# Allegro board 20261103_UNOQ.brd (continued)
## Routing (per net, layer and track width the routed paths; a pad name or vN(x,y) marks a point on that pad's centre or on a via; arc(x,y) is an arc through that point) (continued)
VREG_L4A_2P96V: length 46.4
  TOP w0.2: v2(37.96,12.08) 37.96,13.32 PMIC1.Y14
  G2 w0.203: v2(37.96,12.08) v3(39.02,12.08)
  S3 w0.2: v3(25.78,33.67) 25.77,33.67 v4(25.77,33.96)
  S3 w0.203: v3(39.02,12.08) v4(39.02,11.79)
  S6 w0.3: v4(39.02,11.79) 39.37,11.44 39.37,10.62 38.86,10.11 27.37,10.11 21.75,15.73 21.75,32.01 22.14,32.41 25.11,32.41 25.55,32.85 25.55,33.74 v4(25.77,33.96) 25.77,34.11 v1(25.67,34.21)
VREG_L5A_1P232V: length 6.6
  TOP w0.16: 33.07,14.15 33.88,14.96 33.88,14.96 34.05,15.13 34.05,15.13 PMIC1.P2
  TOP w0.2: v3(32.94,14.15) 33.07,14.15
  TOP w0.203: v3(33.45,34.41) 33.38,34.48 SOC1.F15 ; SOC1.AB11 26.97,36.25 v3(26.92,36.3) 26.97,36.36 SOC1.AB10
  S3 w0.127: 27.17,36.29 27.15,36.26 27.13,36.26 27.03,36.16 27.03,36.15 v3(26.97,36.08) ; 27.17,36.29 27.21,36.32 27.23,36.32 27.23,36.39 27.19,36.39 27.19,36.38 v4(27.18,36.38) ; 27.17,36.29 26.99,36.29 26.97,36.31 26.92,36.31 26.92,36.3 v3(26.92,36.3)
  S3 w0.2: v3(30.65,30.98) 30.57,30.98 30.57,31.06 v4(30.45,31.18) 30.35,31.28 v3(30.17,31.28) ; v4(33.82,34.29) 33.82,34.29 33.82,34.3 33.81,34.3 33.81,34.3 33.56,34.3 v3(33.45,34.41) ; v3(29.37,37.68) 29.37,37.63 29.55,37.45 v4(29.55,37.45) 29.77,37.66 v3(29.77,37.68)
  S3 w0.304: v3(32.94,14.15) 32.27,14.15 32.27,14.16 v4(32.27,14.16)
  S6 w0.2: v4(33.82,34.29) 33.82,34.29 33.82,34.3 33.81,34.3 33.66,34.15 v1(33.56,34.15)
  G7 w0.2: v1(29.29,37.68) v1(29.83,37.68)
  BOTTOM w0.203: C1934.1 33.52,34.15 33.53,34.15 v1(33.56,34.15)
  vias: v1(26.37,36.69) v1(26.92,36.66) v1(26.92,36.14) v1(30.63,31.54) v1(30.57,30.93) v1(30.6,30.49) v5(26.37,36.69) v5(26.92,36.66) v5(26.92,36.14) v5(30.63,31.54) v5(30.57,30.93) v5(30.6,30.49)
VREG_L6A_0P9V: length 33.7
  TOP w0.16: PMIC1.R1 34.16,14.76 34.01,14.61
  TOP w0.2: 34.01,14.61 33.05,13.64 C814.1
  S3 w0.127: v3(32.97,34.48) 33.09,34.36 33.09,34.24 v4(33.1,34.24)
  S3 w0.2: v4(30.04,30.48) v3(29.77,30.48)
  S3 w0.304: v3(32.94,13.75) 32.93,13.76 v4(32.61,13.76)
  S6 w0.2: 33.16,34.28 33.35,34.48 v1(33.35,34.63) 33.35,34.9 v1(33.3,34.95) ; 33.16,34.28 33.07,34.19 33.07,34.26 33.08,34.26 33.08,34.24 v4(33.1,34.24) ; 33.16,34.28 33.16,34.19 33.48,33.87 33.92,33.87 v5(34.32,33.48)
  S6 w0.3: 30.4,14.61 30.84,15.04 30.84,27.04 30.09,27.78 30.09,30.15 30.19,30.25 v1(30.19,30.25) 30.04,30.4 v4(30.04,30.48)
  S6 w0.304: v4(32.61,13.76) 30.69,13.76 30.4,14.05 30.4,14.61
  G7 w0.3: v5(34.32,33.48) 34.65,33.15 34.65,29.58 34.38,29.32 30.87,29.32 30.19,29.99 v1(30.19,30.25)
VREG_L7A_0P664V: length 4.3
  TOP w0.06: 32.96,14.66 v3(33.02,14.59)
  TOP w0.15: v3(33.02,14.59) 33.11,14.59 33.17,14.66 ; PMIC1.N3 34.14,15.41
  TOP w0.2: v3(32.17,36.08) v3(32.17,36.48) ; C815.1 33.17,14.66 33.93,15.41 34.14,15.41
  S3 w0.2: v4(32.17,37.16) v3(32.17,36.88)
  S3 w0.254: v4(33.3,14.59) 33.09,14.59 v3(33.02,14.59)
  V5 w0.3: v4(32.17,37.16) 32.17,36.76 v4(31.89,36.48)
  BOTTOM w0.05: C1845.1 32.26,37.55
  BOTTOM w0.203: v1(32.3,37.46) 32.26,37.46 32.26,37.49 32.26,37.55
  vias: v1(31.65,36.66) v1(32.2,36.6) v5(31.65,36.66) v5(32.2,36.6)
VREG_L8A_1P0V: length 5.3
  TOP w0.18: PMIC1.J5 35.29,16.55 34.61,16.55
  TOP w0.2: 34.61,16.55 34.43,16.37 33.54,16.37 ; v3(28.17,34.08) v3(28.17,33.68)
  TOP w0.254: 33.54,16.37 33.22,16.05 v3(31.88,16.05)
  S3 w0.2: v3(28.17,33.68) 28.2,33.68 v4(28.4,33.89) ; v3(31.88,16.05) v4(31.88,16.33)
  V5 w0.2: v4(28.4,33.89) 28.06,33.89 v4(27.87,34.08)
  S6 w0.203: v1(28.81,33.93) 28.83,33.93 28.83,33.93 28.85,33.93 28.85,33.93
  vias: v1(28.21,34.11) v5(28.21,34.11)
VREG_L9A_1P0V: length 4.1
  TOP w0.2: C817.1 33.3,15.67 33.7,16.07 34.64,16.07 PMIC1.L3
  S3 w0.2: v3(32.94,15.75) v4(32.94,16.08) ; v4(27.47,33.68) v3(27.77,33.68)
  S6 w0.2: v1(27.21,33.58) 27.22,33.58 27.22,33.58 27.2,33.58 27.24,33.54 27.33,33.54 v4(27.47,33.68)
  BOTTOM w0.2: C1828.1 27.25,33.52 C1827.1 C1826.1
  vias: v1(26.24,33.48) v5(26.24,33.48)
VREG_L10A_1P3V: length 54
  TOP w0.05: v3(32.26,37.67) 32.22,37.67 32.21,37.68 SOC1.J7
  TOP w0.16: PMIC1.H6 35.57,16.82 35.42,16.82 35.41,16.83 35.18,16.83 35.17,16.82 34.85,16.82
  TOP w0.18: 33.85,16.82 34.85,16.82
  TOP w0.203: v3(4.64,59.37) 5.91,59.37 U2901.15
  TOP w0.254: 33.85,16.82 33.48,16.82 33.1,16.43 31.6,16.43 31.34,16.18 v3(31.34,16.05)
  S3 w0.2: v3(32.26,37.67) 32.22,37.67 v4(31.99,37.67) 31.72,37.67 v3(31.71,37.68)
  S3 w0.203: v4(30.96,14.4) 30.45,14.91 30.45,15.77 30.74,16.05 v3(31.34,16.05) ; v4(7.47,58.83) 5.18,58.83 v3(4.64,59.37)
  V4 w0.3: v4(20.15,56.12) 19.62,55.59 19.62,54.5 21.04,53.08 21.04,47.75 23.93,44.86 28.89,44.86 31.55,42.2 31.55,38.89 31.99,38.45 v4(31.99,37.67)
  V5 w0.524: v4(20.15,56.12) 11.88,56.12 9.97,58.03 8.27,58.03 v4(7.47,58.83)
  S6 w0.2: v4(31.99,37.67) 31.68,37.98 v1(31.68,38.09)
  BOTTOM w0.2: C1935.1 v1(31.68,38.09)
VREG_L11A_1P0V: length 72.9
  TOP w0.254: v3(33.05,15.16) 33.22,15.16 33.82,15.76 34.38,15.76 PMIC1.M2
  S3 w0.203: v3(37.21,46.99) 37.35,46.99 v4(37.61,46.73) 38.22,46.12 v4(38.22,42.01)
  S3 w0.254: v3(33.05,15.16) 32.89,15.16 v4(32.64,14.91)
  V4 w0.254: v4(24.71,9.93) 25.76,10.97 27.25,10.97 28.35,12.06 28.96,12.06 29.69,12.8 29.69,14.63 29.9,14.83 31.52,14.83 31.78,14.58 32.3,14.58 v4(32.64,14.91)
  S6 w0.203: v1(37.61,47.02) v4(37.61,46.73)
  S6 w0.254: v4(38.22,42.01) 37.74,42.01 36.88,41.15 34.75,41.15 33.5,39.9 22.56,39.9 20.55,37.9 20.55,13.93 24.55,9.93 v4(24.71,9.93)
  BOTTOM w0.381: R3009.1 38.97,50.82 38.97,48.38 v1(37.61,47.02)
VREG_L12A_0P9V: length 4.3
  TOP w0.16: 33.05,13.13 34.82,14.9 34.82,14.94 PMIC1.P4
  TOP w0.2: v3(32.94,13.13) 33.05,13.13
  S3 w0.2: v3(30.97,30.48) 31.15,30.3 31.15,30.29 31.19,30.25 31.19,30.23 v4(31.4,30.03) ; v4(32.05,30.96) 31.86,30.96 v3(31.79,30.89)
  S3 w0.304: v3(32.94,13.13) v4(33.37,13.13)
  vias: v1(31.4,29.7) v1(32.25,31.16) v1(32.24,30.7) v1(32.23,30.19) v1(32.22,29.72) v5(31.4,29.7) v5(32.25,31.16) v5(32.24,30.7) v5(32.23,30.19) v5(32.22,29.72)
VREG_L13A_1P8V: length 73.6
  TOP w0.127: 28.17,34.88 27.74,34.88 27.39,34.52 v3(27.39,34.46) 27.54,34.31 27.77,34.08 SOC1.Y16
  TOP w0.203: v3(23.06,57.73) 23.04,57.7 U2901.39 ; v3(37.82,13.77) 37.79,13.74 37.72,13.74 37.7,13.72 PMIC1.W13
  S3 w0.2: v4(27.08,34.54) 27.16,34.46 v3(27.39,34.46) ; v3(26.17,36.48) 26.33,36.32 26.41,36.32 ; 26.41,36.32 v4(26.44,36.32) ; 26.41,36.32 v3(26.17,36.08) ; v3(28.12,34.9) 28.14,34.9 28.17,34.93 v4(28.17,35.24) ; v4(31.64,37.03) 31.64,37.15 v3(31.77,37.28) ; v3(29.37,30.48) 29.08,30.48 v4(29.07,30.48) ; v3(30.97,30.88) 31.03,30.88 31.12,30.79 31.37,30.79 v4(31.39,30.77) 31.39,30.69 31.37,30.67 v3(31.37,30.48) ; v3(30.17,32.88) 30.17,32.63 v4(30.15,32.61) ; v4(25.89,35.28) v3(26.17,35.28)
  S3 w0.203: v3(23.06,57.73) 21.83,56.49 21.83,54.51 23.45,52.88 v4(23.68,52.88)
  S3 w0.3: v3(37.82,13.77) 37.82,11.47 37.45,11.1 v3(37.45,10.99) 37.45,10.66 37.7,10.41 37.7,9.43 v4(37.64,9.37)
  V5 w0.2: v4(31.39,30.77) 31.03,30.77 30.85,30.95 30.85,31.36 30.55,31.66 30.55,32.4 30.34,32.61 v4(30.15,32.61)
  V5 w0.203: v4(12.09,53.77) 12.51,54.19 20.25,54.19 21.95,52.48 23.28,52.48 v4(23.68,52.88)
  S6 w0.2: v4(30.15,32.61) 30.34,32.8 30.34,32.91 v1(30.32,32.91) ; v1(26.73,34.59) 26.98,34.59 27.03,34.54 v4(27.08,34.54) ; v4(37.64,9.37) 37.27,9.37 37.25,9.35 ; v1(28.14,34.95) 28.12,34.95 28.12,35.19 v4(28.17,35.24) ; v1(25.86,35.74) 25.89,35.71 v4(25.89,35.28) 25.89,35.06 v1(25.69,34.85) ; v1(29.45,30.42) 29.12,30.42 v4(29.07,30.48) ; v4(31.39,30.77) 31.42,30.77 v1(31.6,30.95) ; v1(25.86,36.82) v1(25.86,36.28) 26.4,36.28 v4(26.44,36.32) ; v1(31.59,37.56) 31.64,37.51 v4(31.64,37.03)
  S6 w0.203: v4(12.09,53.77) 10.4,52.08 9.2,52.08 8.76,51.64 8.76,46.73 9.53,45.96 9.53,41.5 12.06,38.96 v1(12.93,38.96) ; v1(23.42,39.27) 23.42,36.2
  BOTTOM w0.203: v1(26.73,34.59) 26.74,34.58 C1917.1 ; v1(12.93,38.96) 13.94,38.96 15.61,40.63 17.95,40.63 18.37,41.05 21.64,41.05 v1(23.42,39.27) ; C1912.1 28.16,34.97 v1(28.14,34.95) ; v1(31.6,30.95) 31.6,30.86 31.7,30.76 ; C1939.1 25.69,35.06 v1(25.69,34.85)
  vias: v1(21.39,26.94) v1(21.39,26.61) v2(30.15,34.5) v5(21.39,26.94) v5(21.39,26.61)
VREG_L14A_1P8V: length 30
  TOP w0.3: v3(37.45,12.08) 37.45,13.26 PMIC1.Y12
  S3 w0.3: v4(37.42,12.36) 37.42,12.1 v3(37.45,12.08)
  S6 w0.254: v4(37.42,12.36) 36.94,12.36 35.32,13.98 35.32,14.43 34.23,15.52 34.23,16.73 34.86,17.36 34.86,22.16 v1(34.08,22.95)
  G7 w0.203: v1(29.22,22.8) 29.47,22.8 29.6,22.67 v1(29.6,21.7)
  BOTTOM w0.203: v1(34.08,22.95) 32.83,21.7 v1(29.6,21.7) ; v1(29.22,22.8) 29.8,22.8 29.94,22.94 29.94,23.66 29.8,23.8 29.22,23.8 EMMC1.P3 EMMC1.N4 EMMC1.M4 28.12,23.4 24.8,23.4 23.72,22.32 EMMC1.C6
  BOTTOM w0.3: v1(34.08,22.95) 34.08,23.58 C2106.1
VREG_L15A_1P8V: length 185.3
  TOP w0.15: v2(26.57,33.28) v2(26.57,33.05) 26.57,32.89 26.13,32.46 ; v3(25.37,33.68) 25.48,33.79 25.49,33.79 25.65,33.96 26.28,33.96 26.44,33.8 26.45,33.79 26.46,33.79 SOC1.AC17 ; 40.11,19.09 PMIC1.B22
  TOP w0.17: 40.11,19.09 41.13,20.12 v3(41.13,20.12)
  TOP w0.2: PMIC1.V8 36.27,13.87 36.27,13.68 ; 26.13,32.46 26.13,31.42 26.27,31.28 v3(26.57,31.28) ; 26.17,33.28 v2(26.57,33.28)
  TOP w0.203: R1313.1 v3(22.71,12.38) ; R1319.1 25.15,12.62 v3(25.38,12.39) ; R1311.1 v3(27.74,15) ; v3(21.57,37.27) R1307.1 R1305.1 R1309.1 R1315.1 R1317.1 ; U2901.17 5.13,57.7 v3(4.64,58.19)
  TOP w0.3: C823.1 C824.1 35.89,12.38 36.27,12.77 36.27,13.68
  G2 w0.2: v2(26.59,33.66) 26.54,33.66 26.27,33.93 26.06,33.93 26.06,33.93 26.01,33.93 25.95,33.99 25.72,33.99 25.65,33.92 25.61,33.92 v3(25.37,33.68)
  S3 w0.127: v4(43.64,37.39) 43.82,37.21 v3(43.86,37.21) ; v3(26.57,31.28) 26.28,31.28 26.27,31.29 26.27,31.23 26.26,31.23 26.26,31.24 v4(26.25,31.24) ; v4(37.72,38.02) 37.55,37.86 37.5,37.86 37.5,37.8 v3(37.46,37.8) ; v3(39.9,37.21) v4(39.9,36.92)
  S3 w0.15: v4(33.09,36.17) 33.28,36.17 v3(33.37,36.08)
  S3 w0.2: v4(27.67,37.68) v3(27.37,37.68) ; v4(32.7,30.83) 32.92,30.83 v3(32.97,30.88) ; v4(43.69,31.13) 43.69,31.18 v3(43.86,31.36) ; v3(30.57,32.88) 30.57,33.17 v4(30.58,33.18) ; v4(25.18,33.87) v3(25.37,33.68) ; v4(46.55,37.87) 46.54,37.86 v3(46.26,37.86) ; v3(46.26,30.71) 46.56,30.71 v4(46.56,30.71) ; v4(29.67,30.08) v3(29.37,30.08) ; v3(37.46,30.71) v4(37.18,30.71) ; v4(33.09,32.48) v3(33.37,32.48) ; v3(39.86,31.36) v4(39.86,31.07) ; v4(32.97,30.38) v3(32.97,30.08) ; v4(30.69,38.08) v3(30.97,38.08)
  S3 w0.203: v3(25.38,12.39) 22.73,12.39 v3(22.71,12.38) 20.57,12.38 v4(20.45,12.5) ; v3(4.64,58.19) 5.17,57.66 v4(6.58,57.66) ; v3(34.12,46.39) 34.03,46.48 v4(34.03,46.83) ; v3(21.57,37.27) 20.9,37.27 20.61,36.98 18.05,36.98 17.55,37.48 14.68,37.48 v4(14.09,38.07) ; v4(20.38,12.87) 22.56,15.05 27.69,15.05 v3(27.74,15)
  S3 w0.3: v4(36.41,11.85) 36.38,11.88 v3(36.38,12.12) ; v3(41.13,20.12) v4(41.36,20.35)
  S3 w0.524: v6(45.57,51.13) 46.58,51.13 46.93,51.48 46.93,54.63 45.96,55.6 43.74,55.6 40.85,52.71 40.12,52.71 39.84,52.43 v4(39.22,52.43)
  V4 w0.524: v4(25.3,45.49) 24.08,45.49 21.7,47.87 21.7,52.12 v4(22.57,52.99)
  V5 w0.203: 11.41,54.93 11.59,54.76 v4(11.59,54.16)
  V5 w0.5: v4(7.09,57.65) 7.09,57.31 9.47,54.93 20.63,54.93 v4(22.57,52.99)
  S6 w0.1: v1(19.63,13.36) 19.63,13.04 v4(19.66,13.01)
  S6 w0.2: v1(29.61,29.77) 29.61,30.02 v4(29.67,30.08) ; v4(37.72,38.02) 37.72,38.03 v1(37.72,38.41) ; v1(25.19,33.02) v1(25.19,33.53) 25.19,33.86 v4(25.18,33.87) ; v4(30.69,38.08) 31.29,38.08 31.45,38.25 31.45,38.26 31.6,38.41 32.28,38.41 32.28,37.87 32.56,37.59 32.56,37.1 32.66,37 32.66,37 32.85,36.81 33.08,36.58 33.08,36.14 33.08,36.14 33.08,36.17 v4(33.09,36.17) ; v1(39.85,31.38) 39.85,31.08 v4(39.86,31.07) ; v1(33.26,30.73) 33.13,30.85 33.13,31.02 33.12,31.03 ; v1(26.43,31.03) 26.27,31.19 26.27,31.23 26.26,31.23 26.26,31.24 v4(26.25,31.24) ; v1(30.96,32.96) 30.96,32.92 ; 30.96,32.92 31.11,32.92 31.37,32.66 31.88,32.66 32.06,32.48 32.17,32.48 32.2,32.46 32.86,32.46 32.91,32.41 33.02,32.41 v4(33.09,32.48) 33.24,32.33 v1(33.24,32.24) 33.12,32.12 33.12,31.67 33.16,31.64 33.16,31.43 33.12,31.4 33.12,31.03 ; 30.96,32.92 30.7,33.18 v4(30.58,33.18) ; 33.12,30.94 33.12,31.03 ; v1(37.18,31.06) v4(37.18,30.71)
  S6 w0.203: v4(29.61,63.05) 29.76,62.9 v1(29.76,62.63) 29.68,62.55 v1(29.68,61.49) ; 11.4,27.67 11.4,30.77 v4(10.72,31.45) ; 11.4,27.67 v1(11.16,27.91) ; 11.4,27.67 v1(11.4,27.11) ; v4(11.23,38.07) 11.45,38.28 13.88,38.28 v4(14.09,38.07) ; v1(11.59,53.88) v4(11.59,54.16)
  S6 w0.3: v4(39.9,36.92) 39.92,36.94 v1(39.92,37.36)
  S6 w0.5: v4(39.22,52.43) 38.99,52.2 38.99,51.69 38.05,50.75 36.91,50.75 36.63,50.47 35,50.47 34.01,49.48 34.01,48.37 35.17,47.21 v1(35.17,47.17) 34.37,47.17 v4(34.03,46.83) 33.1,45.9 28.82,45.9 28.41,45.49 v4(25.3,45.49)
  S6 w0.524: v4(13.6,3.88) v1(13.26,3.88) v1(12.99,3.88)
  BOTTOM w0.2: 15.55,37.32 U1101.1
  BOTTOM w0.203: R2606.2 15.48,52.33 R2605.2 12.96,52.33 11.59,53.7 v1(11.59,53.88) ; 27.73,37.68 C1833.1 27.51,37.91 ; 25.84,30.86 C1841.1 ; C1841.1 25.61,31.09 ; C1841.1 26.07,31.09 ; 23.6,32.78 TP2610.1 ; TP2610.1 24.08,33.26 ; TP2610.1 23.6,33.74 ; TP2610.1 23.12,33.26 ; 26.35,30.86 C1834.1 26.13,31.09 ; v1(29.76,62.63) 29.87,62.74 R2609.2 ; MCU1.A6 16.2,24.11 C2516.1 16.82,24 C2515.1 17.17,23.92 17.43,23.66 17.43,23.62 18.72,23.62 19.65,22.69 19.65,16.06 19.99,15.72 19.99,14.43 19.89,14.33 ; 29.61,29.55 v1(29.61,29.77) ; C2514.1 v1(11.16,27.91) ; 24.96,33.53 v1(25.19,33.53) 25.19,33.3 ; R1102.1 20.34,32.32 ; R1102.1 20.03,32.62 ; R1102.1 20.03,32.02 ; v1(30.3,25.8) R2114.1 ; 25.19,33.25 v1(25.19,33.02) 24.96,33.02
  BOTTOM w0.381: v1(35.17,47.17) 35.21,47.17 37.35,49.31 R3012.1
  BOTTOM w0.524: v1(12.99,3.88) v1(12.7,3.88) 10.07,3.88 9.52,4.43 9.52,8.08
  BOTTOM w0.6: 16.14,34.64 U1102.1 15.69,33.91
  vias: v1(12.84,4.05) v1(12.85,3.7) v1(13.12,4.05) v1(13.13,3.7) v1(18.8,13.77) v1(18.95,13.56) v1(19.08,13.77) v1(19.1,13.36) v1(19.23,13.56) v1(19.33,13.77) v1(19.38,13.36) v1(19.48,13.56) v1(19.61,13.77) v1(19.76,13.56) v1(19.91,13.36) v1(25.8,31.09) v1(27.77,37.96) v1(30.35,38.18) v1(33.28,30.22) v2(26.24,33.27) v4(6.79,58.03) v4(13.99,3.88) v4(14.37,3.88) v4(19.34,6.94) v4(19.77,6.95) v4(20.02,12.98) v4(20.1,12.6) v4(20.21,6.96) v5(12.84,4.05) v5(12.85,3.7) v5(13.12,4.05) v5(13.13,3.7) v5(18.8,13.77) v5(18.95,13.56) v5(19.08,13.77) v5(19.1,13.36) v5(19.23,13.56) v5(19.33,13.77) v5(19.38,13.36) v5(19.48,13.56) v5(19.61,13.77) v5(19.76,13.56) v5(19.91,13.36) v5(25.8,31.09) v5(27.77,37.96) v5(30.35,38.18) v5(33.28,30.22) v6(45.75,59.87) v6(45.75,59.41) v6(45.76,58.96) v6(45.75,58.52) v6(46.14,59.68)
VREG_L16A_1P8V: length 1.4
  TOP w0.254: C825.1 36.93,12.08 36.93,12.58 36.71,12.8 PMIC1.Y10
VREG_L17A_3P0V: length 1.4
  TOP w0.2: C826.1 38.41,12.18 PMIC1.Y16
VREG_L18A_1P8V: length 1.6
  TOP w0.2: PMIC1.Y22 39.55,12.88 C827.1
VREG_L19A_1P8V: length 1.6
  TOP w0.2: C828.1 39.22,12.28 39.22,13.11 PMIC1.Y20
VREG_L20A_2P96V: length 31.9
  TOP w0.2: PMIC1.V16 38.39,14.01 38.18,14.01 38.18,14.01 38.17,14.01 v3(38.17,14.01)
  S3 w0.203: v4(27.91,10.97) 27.91,9.58 28.8,8.69 37.42,8.69 38.1,9.37 38.1,10.67 37.96,10.81 C829.1
  S3 w0.3: v3(38.17,14.01) 38.25,13.94 38.25,11.3 v3(38.05,11.1)
  BOTTOM w0.203: EMMC1.F5 24.95,22.53 ; 24.95,22.53 EMMC1.E6 ; 24.95,22.53 25.04,22.43 26.47,22.43 26.72,22.17 EMMC1.J10 ; v1(27.61,19.96) 26.95,19.96 26.72,20.19 EMMC1.J10 ; v1(27.22,20.8) EMMC1.J10
  BOTTOM w0.3: C2104.1 C2103.1 C2105.1 31.37,19.61 29.56,17.8 29.45,17.8 v1(27.5,17.8) v1(27.28,17.8)
  vias: v2(37.9,10.95) v3(37.9,10.95)
VREG_L21A_2P96V: length 28.8
  S3 w0.2: 37.42,13.44 37.42,13.83 37.62,14.03 v3(37.62,14.22) ; v4(31.27,31.28) v3(30.97,31.28)
  S3 w0.304: 37.07,11.66 37.05,11.66 37.05,12.54 37.42,12.91 37.42,13.44 ; 37.07,11.66 v4(37.16,11.66) ; 37.07,11.66 37.07,11.13 v3(36.93,11)
  S6 w0.2: 31.01,29.91 31.01,31.03 v4(31.27,31.28) 31.43,31.44 v1(31.52,31.44)
  S6 w0.3: 31.01,29.91 31.01,29.59 33.2,27.4 33.2,17.12
  S6 w0.304: 33.2,17.12 33.32,17 33.32,15.17 33.71,14.78 33.71,14.25 32.99,13.54 32.99,13.29 32.99,13.29 32.99,12.9 33.21,12.69 36.13,12.69 v4(37.16,11.66)
VREG_L22A_3P3V: length 86.8
  TOP w0.203: v3(36.93,26.59) 46.29,26.59 47.45,27.75 47.45,40.87 v3(47.5,40.92)
  TOP w0.304: v3(39.55,11.04) 39.55,11.04 C831.1
  S3 w0.203: v4(37.39,27.13) 37.39,27.05 v3(36.93,26.59) ; v3(47.5,40.92) v4(47.5,40.64)
  S3 w0.3: v3(39.55,11.04) 39.5,11.1 39.5,13.35 38.96,13.89
  S3 w0.304: 38.96,13.89 38.96,13.89 v3(38.96,14.01) 38.96,14.15 38.95,14.16 38.95,14.37 v4(38.9,14.41)
  V4 w0.203: v4(47.5,40.64) 46.1,42.04 46.1,53.86 44.86,55.1 43.62,55.1 41.13,57.59 39.9,57.59 39.37,57.06 v4(39.37,56.69)
  S6 w0.203: v4(38.99,56.69) v1(38.71,56.69)
  S6 w0.4: v4(38.9,14.41) 40.2,13.12 41.27,13.12 41.77,13.62 41.77,15.14 40.03,16.88 40.03,20.29 38.55,21.77 38.55,25.97 v4(37.39,27.13)
  BOTTOM w0.524: v1(38.3,56.69) 37.64,57.35 26.42,57.35 25.63,56.57 23.52,56.57 v6(23.37,56.41)
  vias: v1(38.51,56.69) v2(22.89,54.64) v2(22.89,54.43) v2(22.89,54.23) v3(22.89,54.64) v3(22.89,54.43) v3(22.89,54.23) v4(23.55,53.51) v4(23.95,53.51) v5(38.51,56.69) v6(23,56.6)
VREG_RFCLK: length 2.3
  TOP w0.16: 34.9,12.57 35.58,13.25 35.58,13.98 35.57,13.99 PMIC1.V6
  TOP w0.2: 34.9,12.57 34.85,12.52 C706.1
VREG_RFCLK2: length 3.4
  S3 w0.15: v3(34.85,11.48) 34.85,12.1 35.41,12.66 35.41,14.4 v3(35.58,14.57)
VREG_S1A_0P8V: length 12.7
  TOP w0.2: v2(28.17,32.88) 28.17,32.48 ; v2(28.17,32.88) v3(27.77,32.88) ; v2(28.17,32.88) v3(28.17,33.28) v4(27.77,33.28) v3(27.77,32.88) ; 28.17,32.48 v2(27.77,32.48) ; 28.17,32.48 v2(28.17,32.08) SOC1.Y21 ; v2(27.77,32.48) v3(27.77,32.88) ; v2(27.77,32.48) SOC1.Y21 ; 28.97,32.08 v2(28.97,32.48) v3(28.97,32.88) ; v3(27.37,30.08) v2(27.37,30.48) v3(27.37,30.88) ; v3(27.37,30.88) v2(27.37,31.28) ; v3(27.37,30.88) v2(27.77,30.88) v3(27.77,31.28) ; SOC1.R22 v3(29.77,32.48) ; v2(27.77,31.68) v3(27.77,31.28) ; v2(27.77,31.68) v3(27.37,31.68) ; v2(27.77,31.68) SOC1.Y21 ; v3(27.77,31.28) v2(27.37,31.28) ; v2(27.37,31.28) v3(27.37,31.68) ; v3(27.37,31.68) v2(27.37,32.08) SOC1.Y21
  S3 w0.2: v4(28.98,31) 28.97,31.02 v3(28.97,31.28) ; v3(28.89,32.13) 28.95,32.13 28.97,32.15 v4(28.97,32.44) ; v4(29.75,32.15) 29.76,32.15 29.76,32.15 29.77,32.15 29.77,31.65 v3(29.72,31.65)
  S6 w0.2: v1(28.53,30.91) 28.63,31 v4(28.98,31)
  BOTTOM w0.127: v1(27.7,32.17) 27.77,32.24 C1709.1
  BOTTOM w0.203: 28.99,30.87 28.99,30.87 28.85,30.73 28.85,30.76 v1(28.83,30.76)
  vias: v1(27.12,29.57) v1(27.42,30.81) v1(27.45,31.85) v1(27.45,31.41) v1(27.63,30.18) v1(27.77,32.97) v1(27.79,30.38) v1(27.9,33.54) v1(27.88,28.97) v1(27.96,31.85) v1(27.95,31.38) v1(28.13,32.44) v1(28.27,33.03) v1(29.29,32.46) v1(29.65,31.89) v1(29.82,32.42) v2(27.77,32.08) v2(28.15,32.49) v2(39.14,23.37) v2(39.11,23.14) v2(39.11,22.9) v2(39.37,23.38) v2(39.65,23.37) v2(39.62,22.93) v2(39.88,23.37) v2(40.13,23.37) v2(40.12,22.93) v2(40.39,23.37) v2(40.61,23.34) v2(40.64,23.11) v2(40.64,22.91) v3(27.29,31.48) v3(27.42,30.68) v3(27.51,31.85) v3(27.67,32.3) v3(27.67,31.09) v3(27.77,32.08) v3(27.83,31.89) v3(27.9,32.3) v3(28.09,33.09) v3(28.15,32.49) v3(39.14,23.37) v3(39.11,23.14) v3(39.11,22.9) v3(39.37,23.38) v3(39.65,23.37) v3(39.62,22.93) v3(39.88,23.37) v3(40.13,23.37) v3(40.12,22.93) v3(40.39,23.37) v3(40.61,23.34) v3(40.64,23.11) v3(40.64,22.91) v4(27.35,32.11) v4(27.35,31.16) v4(27.35,30.38) v4(27.77,32.58) v4(27.77,31.58) v4(27.77,30.77) v4(28.15,32.78) v4(28.09,32.1) v4(39.38,23.11) v4(39.37,22.73) v4(39.87,23.08) v4(39.87,22.71) v4(40.36,23.09) v4(40.37,22.73) v5(27.12,29.57) v5(27.42,30.81) v5(27.45,31.85) v5(27.45,31.41) v5(27.63,30.18) v5(27.77,32.97) v5(27.79,30.38) v5(27.9,33.54) v5(27.88,28.97) v5(27.96,31.85) v5(27.95,31.38) v5(28.13,32.44) v5(28.27,33.03) v5(29.29,32.46) v5(29.65,31.89) v5(29.82,32.42)
VREG_S2A_0P8V: length 15.2
  TOP w0.2: 30.57,33.77 SOC1.N15 v3(30.57,34.52) ; 30.57,33.77 SOC1.N17 ; 30.57,33.77 v3(30.55,33.77) ; v3(27.77,35.28) v2(27.77,35.68) v3(27.77,36.08) v2(27.77,36.48) v2(27.77,36.88) v3(27.77,37.28) ; v3(29.37,32.88) 29.37,33.06 29.77,33.46 SOC1.R17 v2(29.77,34.08) SOC1.R15 SOC1.R13 v2(29.77,35.68) v3(29.77,36.08) v2(29.77,36.48) ; v3(30.57,35.28) v3(30.57,36.08) v3(30.57,36.88) ; v2(29.77,36.48) v3(29.37,36.48) ; v2(29.77,36.48) v3(29.77,36.88) ; v3(31.77,36.08) v2(31.77,35.68) v3(31.77,35.28) v2(31.77,34.88) v3(31.77,34.48) v2(31.77,34.08) v3(31.77,33.68) v2(31.77,33.28)
  S3 w0.2: v3(27.77,35.28) 27.77,34.98 27.76,34.97 27.76,34.97 v4(27.75,34.97) ; v3(31.74,31.71) 31.77,31.71 31.77,31.94 31.74,31.96 v4(31.74,32.04) ; v3(27.77,36.08) 27.77,35.81 27.79,35.79 27.72,35.79 v4(27.73,35.79) ; v4(29.77,36.58) 29.77,36.62 29.77,36.63 v3(29.77,36.88) ; v4(30.97,32.58) v3(30.97,32.88)
  S3 w0.203: 30.56,34.47 30.57,34.48 v3(30.57,34.52)
  S6 w0.1: 26.75,38.71 27.07,38.71 v1(27.13,38.77)
  S6 w0.2: v1(31.52,31.79) 31.58,31.79 31.74,31.96 v4(31.74,32.04)
  BOTTOM w0.203: v1(31.73,33.59) 31.86,33.46 C1815.1 ; C1811.1 31.83,33.8 v1(31.84,33.79) ; v1(27.48,35.03) 27.51,35.07 C1807.1 ; C1813.1 27.45,35.67 27.43,35.69 27.43,35.76 27.45,35.76 27.45,35.88 v1(27.45,35.88)
  vias: v1(27.4,36.74) v1(27.55,36.15) v1(29.49,36.69) v1(29.52,36.11) v1(29.55,35.6) v1(29.64,35.23) v1(29.58,34.72) v1(29.7,33.91) v1(29.86,33.54) v1(30.08,36.63) v1(30.47,36.78) v1(30.5,34.62) v1(30.66,35.51) v1(30.66,34.46) v1(31.83,36.06) v1(31.77,35.19) v1(33.83,29.99) v1(34.2,29.98) v2(29.7,33.7) v2(29.77,35.28) v2(29.77,34.48) v2(36.05,22.92) v2(36.31,23.34) v2(36.28,22.92) v2(36.56,22.92) v2(36.82,23.34) v2(36.85,22.92) v2(37.11,22.91) v2(37.33,23.37) v2(37.33,23.14) v2(37.33,22.92) v3(29.68,36.27) v3(29.68,33.9) v3(29.7,33.7) v3(29.77,35.48) v3(29.77,35.28) v3(29.77,34.68) v3(29.77,34.48) v3(36.05,22.92) v3(36.31,23.34) v3(36.28,22.92) v3(36.56,22.92) v3(36.82,23.34) v3(36.85,22.92) v3(37.11,22.91) v3(37.33,23.37) v3(37.33,23.14) v3(37.33,22.92) v4(27.65,36.85) v4(27.65,36.45) v4(29.42,33.34) v4(29.68,34.19) v4(29.77,35.78) v4(29.77,34.98) v4(30.58,36.52) v4(30.57,35.78) v4(30.57,34.91) v4(30.61,34.16) v4(31.77,35.7) v4(31.77,34.91) v4(31.77,34.08) v4(34.03,29.71) v4(36.09,23.56) v4(36.07,23.2) v4(36.56,23.56) v4(36.56,23.21) v4(37.04,23.56) v4(37.05,23.18) v5(27.4,36.74) v5(27.55,36.15) v5(29.49,36.69) v5(29.52,36.11) v5(29.55,35.6) v5(29.64,35.23) v5(29.58,34.72) v5(29.7,33.91) v5(29.86,33.54) v5(30.08,36.63) v5(30.47,36.78) v5(30.5,34.62) v5(30.66,35.51) v5(30.66,34.46) v5(31.83,36.06) v5(31.77,35.19) v5(33.83,29.99) v5(34.2,29.98)
VREG_S3A_1P352V: length 9.7
  TOP w0.16: v3(35.29,15.41) 35.01,15.7 PMIC1.K4
  TOP w0.203: v3(38.38,18.97) 38.28,18.97 v3(38.12,18.81)
  G2 w0.203: v3(38.38,18.97) 38.22,18.81 v3(38.12,18.81)
  S3 w0.1: 30.48,20.04 30.29,20.04 v3(30.18,20.15)
  S3 w0.2: v3(36.99,17.68) v4(37.19,17.48) 37.25,17.54 37.5,17.54 37.95,17.99 37.95,18.63 v3(38.12,18.81)
  S3 w0.203: v4(38.46,19.23) 38.46,19.23 38.46,19.18 ; v4(35.56,17.18) 35.37,17.18 v3(35.29,17.11) ; v3(38.12,18.81) 38.12,19.08 v4(38.12,19.08) ; v3(34.89,16.26) 34.6,16.26 v4(34.58,16.28) ; v4(34.98,15.27) 35.13,15.41 v3(35.29,15.41)
  S6 w0.203: v1(35.1,16.07) 34.92,16.07 34.72,16.28 v4(34.58,16.28) ; v1(37,17.7) 37,17.67 v4(37.19,17.48) ; v1(35.34,15.66) 35.34,15.63 v4(34.98,15.27)
  BOTTOM w0.203: v1(35.1,16.07) C804.1 35.09,15.61 ; v1(38.14,18.8) C801.1 37.31,18.81 37,18.5 v1(37,17.7) C802.1 ; v1(35.34,15.66) 35.13,15.66 35.13,15.65 35.09,15.61 ; 35.09,15.61 C803.1
  vias: v2(29.13,20.97) v2(29.16,20.3) v2(29.16,20.08) v2(29.35,20.97) v2(29.39,20.3) v2(29.39,20.08) v2(29.58,21.23) v2(29.58,20.97) v2(29.61,20.3) v2(29.61,20.08) v2(30.15,21.19) v2(30.15,20.97) v2(30.18,20.37) v3(29.13,20.97) v3(29.16,20.3) v3(29.16,20.08) v3(29.35,20.97) v3(29.39,20.3) v3(29.39,20.08) v3(29.58,21.23) v3(29.58,20.97) v3(29.61,20.3) v3(29.61,20.08) v3(30.15,21.19) v3(30.15,20.97) v3(30.18,20.37) v4(29.23,20.66) v4(29.61,20.66) v4(29.86,21.05) v4(29.89,20.18) v4(29.99,20.66)
VREG_S4A_2P04V: length 10.7
  TOP w0.15: PMIC1.V10 36.43,14.28 36.04,14.28 36.04,14.28
  TOP w0.2: PMIC1.A23 40.58,19 40.62,19 41.66,20.05 v3(41.66,20.12) ; C505.1 42.4,17.58 41.93,17.11 PMIC1.G27 ; v3(40.95,16.55) 41.34,16.93 PMIC1.G27 ; PMIC1.G27 v3(41.52,17.04)
  TOP w0.203: 36.04,14.28 35.9,14.28 ; 35.9,14.28 v3(35.9,14.18) ; 35.9,14.28 PMIC1.U7 ; v3(36.73,14) PMIC1.V10
  S3 w0.1: 29.72,17.62 v3(29.41,17.62)
  S3 w0.15: v3(35.89,11) 35.89,11.03 35.74,11.18 35.74,11.2 35.71,11.23 35.71,12.25 35.9,12.43 v3(35.9,14.18)
  S3 w0.203: v4(36.68,13.68) 36.73,13.72 v3(36.73,14) ; v4(37.29,14.41) 37.29,14.07 v3(37.28,14.07) ; v3(41.52,17.04) 41.52,16.91 41.45,16.84 41.45,16.78 v4(41.43,16.78) ; v3(40.95,16.55) 40.97,16.56 40.97,16.69 v4(41.07,16.79) ; v4(42.09,20.55) 41.66,20.12 v3(41.66,20.12)
  vias: v2(28.4,17.65) v2(28.4,17.4) v2(28.4,16.63) v2(28.4,16.41) v2(28.62,17.65) v2(28.62,17.4) v2(28.62,16.63) v2(28.62,16.41) v2(28.84,17.65) v2(28.84,17.4) v2(28.84,16.63) v2(28.84,16.41) v2(29.41,17.4) v2(29.41,16.7) v2(29.41,16.48) v3(28.4,17.65) v3(28.4,17.4) v3(28.4,16.63) v3(28.4,16.41) v3(28.62,17.65) v3(28.62,17.4) v3(28.62,16.63) v3(28.62,16.41) v3(28.84,17.65) v3(28.84,17.4) v3(28.84,16.63) v3(28.84,16.41) v3(29.41,17.4) v3(29.41,16.7) v3(29.41,16.48) v4(28.44,17.11) v4(28.82,17.09) v4(29.13,17.49) v4(29.13,16.71) v4(29.2,17.09)
VREG_XO: length 2.8
  S3 w0.15: v3(35.18,14.28) 35.18,14.14 35.18,13.65 35.18,12.73 34.3,11.85 v3(34.3,11.85)
VRG_CHG: length 5.5
  S3 w0.2: v3(39.98,14.56) 39.85,14.43 39.85,14.05 40.33,13.57 40.33,9.45 v3(40.46,9.32)
VSNS_S1A_APC_M: length 40.7
  TOP w0.053: v3(38.1,17.65) 38.12,17.67 PMIC1.E15
  S3 w0.066: v3(38.1,17.65) 38.1,17.66 38.31,17.86 38.4,17.86 38.4,17.9 v4(38.37,17.9)
  S6 w0.058: v4(38.37,17.9) 38.6,17.9 38.79,18.08 38.79,18.31 38.63,18.47 38.13,18.47 37.97,18.31 37.97,17.86 38.43,17.4 38.43,16.87 37.89,16.33 36.07,16.33 35.71,15.98 35.71,14.15 37.09,12.78 37.62,12.78 37.84,12.56 37.84,11.57 37.24,10.97 28.85,10.97 27.81,12.01 27.81,26.56 26.65,27.72 26.65,28.41 26.59,28.47 26.49,28.47 26.44,28.53 26.44,28.88
VSNS_S1A_APC_P: length 40.8
  TOP w0.053: v3(38.38,17.51) 38.41,17.48 PMIC1.F16
  S3 w0.066: v4(38.69,17.58) 38.59,17.58 38.52,17.51 v3(38.38,17.51)
  S6 w0.058: v4(38.69,17.58) 38.69,17.8 38.91,18.03 38.91,18.37 38.69,18.59 38.07,18.59 37.84,18.37 37.84,17.8 38.3,17.35 38.3,16.92 37.84,16.46 36.01,16.46 35.59,16.03 35.59,14.1 37.04,12.65 37.57,12.65 37.71,12.51 37.71,11.62 37.18,11.1 28.9,11.1 27.94,12.06 27.94,26.61 26.78,27.78 26.78,28.41 26.84,28.47 26.93,28.47 26.99,28.53 26.99,28.88
VSNS_S2A_CX_M: length 34.1
  S3 w0.066: v4(37.85,16.86) 37.9,16.81 37.97,16.81 37.97,16.79 37.97,16.96 PMIC1.G15 38.12,17.11 38.11,17.11 v3(38.08,17.11)
  S6 w0.051: 37.45,18.04 37.45,18.05 37.45,18.06 37.4,18.16 37.4,18.17 37.4,20.64 v5(37.51,20.75)
  S6 w0.058: v5(29.03,39.24) 28.87,39.24 28.77,39.14 27.89,39.14 27.56,39.48 26.62,39.48 26.62,39.48 26.43,39.48 26.3,39.35 26.3,39.12 ; 37.45,18.04 37.75,17.74 37.75,17.51 37.85,17.41 v4(37.85,16.86)
  G7 w0.051: v5(29.03,39.24) 29.12,39.15 35.52,39.15 36.35,38.32 36.35,29.35 38.05,27.65 38.05,21.55 37.45,20.95 37.45,20.81 v5(37.51,20.75)
VSNS_S2A_CX_P: length 33
  S3 w0.066: v4(37.52,17.18) 37.58,17.12 37.65,17.12 37.65,17.11 37.67,17.11 37.67,17.22 v3(37.84,17.39)
  S6 w0.051: 37.35,17.96 37.33,17.98 37.33,18.04 37.31,18.1 37.29,18.12 37.29,20.64 v5(37.18,20.75)
  S6 w0.058: v5(29.03,38.91) 28.87,38.91 28.77,39.01 27.84,39.01 27.5,39.35 26.85,39.35 26.75,39.25 26.75,39.12 ; 37.35,17.96 37.62,17.69 37.62,17.51 37.52,17.41 v4(37.52,17.18)
  G7 w0.051: v5(37.18,20.75) 37.3,20.87 37.3,21.05 37.9,21.65 37.9,27.55 36.2,29.25 36.2,38.3 35.5,39 29.12,39 v5(29.03,38.91)
VSW_CHG: length 4.5
  TOP w0.2: C609.2 43.03,13.17 L601.1 42.44,12.55 42.11,12.55 41.24,13.42 PMIC1.Y26 PMIC1.W25
WCN_RFCLK2: length 74.9
  TOP w0.066: v3(29.27,13.05) R701.1
  S3 w0.064: v3(29.27,13.05) 27.93,13.05 26.62,11.73 13.81,11.73 12.87,12.67 7.72,12.67 4.52,15.87 4.52,52.86 5.11,53.44 5.11,55.55 4.13,56.53 v3(4.13,62.6)
WCN_RFCLK2_R: length 2.7
  TOP w0.066: R2905.2 4.74,62.5 U2901.13
WCN_SW_CTRL: length 37.1
  TOP w0.066: v3(24.23,61.94) 24.07,62.1 23.42,62.1 23.34,62.02 20.81,62.02 20.32,61.53 17.03,61.53 U2901.5 ; v3(34.36,41.65) 34.3,41.59 32.3,41.59 32.17,41.46 SOC1.J1
  S3 w0.064: v3(24.23,61.94) 24.21,61.94 24.17,61.9 24.17,57.74 25.1,56.81 25.1,51.67 34.36,42.41 v3(34.36,41.65)
WL_CLK_OUT: length 3.1
  TOP w0.066: U2901.21 6.44,53.24 TP2901.1
WL_CMD_CLK: length 27.9
  TOP w0.066: v3(22.12,47.01) 23.76,48.65 23.76,51.9 23.2,52.46 20.9,52.46 20.62,52.73 20.62,55.3 20.83,55.5 U2901.37
  S3 w0.064: v3(22.12,47.01) 22.35,46.78 22.83,46.78 23.2,46.41 26.09,46.41 26.33,46.17 27.69,46.17 32.28,41.58 32.28,39.05 32.11,38.88 v3(31.77,38.88)
WL_CMD_DATA: length 29.4
  TOP w0.066: v3(22.01,46.72) 21.85,46.88 21.85,47.14 23.55,48.84 23.55,51.79 23.12,52.22 20.91,52.22 20.47,52.66 20.47,56.39 20.68,56.6 U2901.38
  S3 w0.064: v3(22.01,46.72) 22.16,46.57 22.75,46.57 23.13,46.19 26.08,46.19 26.27,46 27.65,46 32.11,41.54 32.11,39.17 32,39.06 31.55,39.06 v3(31.37,38.88)
WLAN0_DAC_RSET: length 3.2
  TOP w0.066: R1602.2 35.03,41.13 33.48,41.13 v2(33.21,40.86)
  G2 w0.064: v2(33.05,39.77) 33.17,39.89 33.17,40.82 v2(33.21,40.86)
WLAN_BT_COEX_CLK: length 50.4
  TOP w0.066: v3(24.71,61.67) 24.69,61.65 20.92,61.65 20.4,61.13 11.64,61.13 7.1,56.6 U2901.18
  S3 w0.064: v3(24.71,61.67) 24.71,57.86 25.44,57.13 25.44,51.79 34.98,42.26 34.98,41.41 34.4,40.83 34.4,40.3 33.81,39.7 33.81,39.08 33.21,38.48 v3(31.37,38.48)
WLAN_BT_COEX_DATA: length 50.6
  TOP w0.066: v3(24.45,61.32) 24.3,61.47 21.03,61.47 20.5,60.94 11.67,60.94 6.44,55.71 U2901.19
  S3 w0.051: v3(30.97,38.48) 31.14,38.66 33.11,38.66 33.65,39.2
  S3 w0.064: 33.65,39.2 33.65,39.71 34.23,40.28 34.23,40.92 34.83,41.53 34.83,42.18 25.26,51.74 25.26,57.06 24.45,57.87 v3(24.45,61.32)
WLAN_RX_I_M: length 36.9
  TOP w0.05: SOC1.A3 35.37,39.28 35.55,39.46 35.69,39.46 35.92,39.7 35.92,40.15 v3(36.05,40.28)
  TOP w0.058: U2901.32 18.77,51.2 18.77,50.14 v3(18.57,49.94)
  S3 w0.053: v3(18.57,49.94) 18.6,49.91 v4(18.6,49.66) ; v4(29.06,49.86) 29.22,49.71 30.98,49.71 31.99,48.69 31.99,46.67 32.57,46.09 32.64,46.09 32.82,46.27 32.99,46.27 33.14,46.12 33.14,45.95 32.96,45.78 32.96,45.7 33.03,45.62 33.11,45.62 33.29,45.8 33.46,45.8 33.6,45.66 33.6,45.49 33.43,45.31 33.43,45.23 35.92,42.74 35.92,40.41 v3(36.05,40.28)
  S6 w0.053: v4(18.6,49.66) 18.78,49.84 18.78,50.07 18.95,50.24 19.56,50.24 19.68,50.12 19.68,49.7 19.74,49.65 19.84,49.65 19.9,49.7 19.9,50.12 20.02,50.24 20.22,50.24 20.34,50.12 20.34,49.7 20.4,49.65 20.5,49.65 20.56,49.7 20.56,50.12 20.68,50.24 20.99,50.24 21.55,49.68 26.78,49.68 26.83,49.74 26.83,50.54 26.95,50.66 27.16,50.66 27.28,50.54 27.28,49.74 27.33,49.68 27.44,49.68 27.49,49.74 27.49,50.54 27.61,50.66 27.82,50.66 27.94,50.54 27.94,49.74 27.99,49.68 28.1,49.68 28.15,49.74 28.15,50.54 28.27,50.66 28.48,50.66 28.6,50.54 28.6,49.74 28.65,49.68 28.88,49.68 v4(29.06,49.86)
WLAN_RX_I_P: length 36.8
  TOP w0.05: v3(35.67,40.28) 35.8,40.15 35.8,39.75 35.64,39.59 35.46,39.59 35.37,39.68 SOC1.A2
  TOP w0.058: U2901.33 19.12,51.71 18.9,51.49 18.9,51.2 18.96,51.15 19.02,51.15 19.08,51.09 19.08,50.97 19.02,50.91 18.96,50.91 18.9,50.85 18.9,50.74 18.96,50.68 19.02,50.68 19.08,50.62 19.08,50.5 19.02,50.45 18.96,50.45 18.9,50.39 18.9,50.14 v3(19.1,49.94)
  S3 w0.053: v3(19.1,49.94) 19.08,49.91 v4(19.08,49.66) ; v4(29.06,49.39) 29.27,49.59 30.93,49.59 31.88,48.64 31.88,46.62 32.52,45.98 32.69,45.98 32.87,46.15 32.94,46.15 33.02,46.08 33.02,46 32.84,45.82 32.84,45.65 32.99,45.51 33.16,45.51 33.33,45.68 33.41,45.68 33.49,45.61 33.49,45.53 33.31,45.36 33.31,45.19 35.8,42.69 35.8,40.41 v3(35.67,40.28)
  S6 w0.053: v4(29.06,49.39) 28.88,49.57 28.6,49.57 28.48,49.69 28.48,50.49 28.43,50.54 28.32,50.54 28.27,50.49 28.27,49.69 28.15,49.57 27.94,49.57 27.82,49.69 27.82,50.49 27.77,50.54 27.66,50.54 27.61,50.49 27.61,49.69 27.49,49.57 27.28,49.57 27.16,49.69 27.16,50.49 27.11,50.54 27,50.54 26.95,50.49 26.95,49.69 26.83,49.57 21.5,49.57 20.94,50.12 20.73,50.12 20.67,50.07 20.67,49.65 20.55,49.53 20.35,49.53 20.23,49.65 20.23,50.07 20.17,50.12 20.07,50.12 20.01,50.07 20.01,49.65 19.89,49.53 19.69,49.53 19.57,49.65 19.57,50.07 19.51,50.12 19,50.12 18.9,50.02 18.9,49.84 v4(19.08,49.66)
WLAN_RX_Q_M: length 37.5
  TOP w0.058: U2901.23 8.82,51.24 8.82,50.15 v3(8.61,49.94)
  S3 w0.053: v4(9.5,51.15) 9.32,50.97 9.01,50.97 8.83,50.79 8.83,50.23 8.83,50.23 8.83,50.16 v3(8.61,49.94) ; v3(34.97,40) 34.97,40.35 35.41,40.78 35.41,42.56 31.15,46.82 31.15,48.13 30.4,48.87 30.15,48.87 v4(29.97,49.05)
  S6 w0.053: v4(9.5,51.15) 9.68,50.97 16.09,50.97 16.54,50.52 16.54,49.5 16.89,49.15 27.91,49.15 28.19,48.87 29.79,48.87 v4(29.97,49.05)
WLAN_RX_Q_P: length 37.5
  TOP w0.058: U2901.24 9.13,51.71 8.96,51.54 8.96,50.15 v3(9.17,49.94)
  S3 w0.053: v3(9.17,49.94) 8.95,50.16 8.95,50.28 8.95,50.28 8.95,50.74 9.06,50.85 9.32,50.85 v4(9.5,50.67) ; v3(34.57,40) 34.86,40.29 34.86,40.39 35.29,40.83 35.29,42.51 31.03,46.77 31.03,48.08 30.36,48.75 30.15,48.75 v4(29.97,48.57)
  S6 w0.053: v4(9.5,50.67) 9.68,50.85 16.04,50.85 16.42,50.47 16.42,49.45 16.84,49.03 27.87,49.03 28.15,48.75 29.79,48.75 v4(29.97,48.57)
WLAN_TX_I_M: length 28.4
  TOP w0.058: U2901.29 15.49,51.18 15.49,50.14 v3(15.29,49.94)
  S3 w0.05: 32.79,39.11 v3(32.57,38.88)
  S3 w0.053: 32.79,39.11 32.89,39.11 32.89,39.1 33.12,39.1 33.38,39.36 33.38,40.48 33.38,40.6 33.54,40.76 33.54,42.26 29.77,46.02 29.26,46.02 27.16,48.12 26.8,48.12 v4(26.62,47.94) ; v4(15.32,50.27) 15.29,50.24 v3(15.29,49.94)
  S6 w0.053: v4(26.62,47.94) 26.44,48.12 25.33,48.12 24.92,48.52 16.52,48.52 15.5,49.54 15.5,50.09 v4(15.32,50.27)
WLAN_TX_I_P: length 28.3
  TOP w0.058: U2901.30 15.62,51.27 15.62,50.67 15.68,50.61 15.73,50.61 15.79,50.56 15.79,50.44 15.73,50.38 15.68,50.38 15.62,50.32 15.62,50.14 v3(15.82,49.94)
  S3 w0.05: 33.07,38.99 v3(32.97,38.88)
  S3 w0.053: 33.07,38.99 33.17,38.99 33.49,39.31 33.49,40.43 33.49,40.43 33.49,40.55 33.66,40.72 33.66,42.3 29.82,46.14 29.31,46.14 27.21,48.23 26.8,48.23 v4(26.62,48.41) ; v4(15.8,50.27) 15.82,50.24 v3(15.82,49.94)
  S6 w0.053: v4(15.8,50.27) 15.62,50.09 15.62,49.59 16.56,48.64 24.97,48.64 25.37,48.23 26.44,48.23 v4(26.62,48.41)
WLAN_TX_Q_M: length 29.8
  TOP w0.058: v3(11.94,49.94) 12.14,50.14 12.14,51.23 U2901.26
  S3 w0.05: v3(32.97,39.28) 32.82,39.43 32.82,40.43 32.83,40.43 32.83,40.44
  S3 w0.053: 32.83,40.44 32.83,41.65 27.34,47.13 26.28,47.13 25.58,47.83 23.49,47.83 v4(23.31,48.01) ; v3(11.94,49.94) 11.94,49.69 v4(11.97,49.66)
  S6 w0.053: v4(23.31,48.01) 23.12,47.82 22.71,47.82 22.36,48.16 16.24,48.16 14.09,50.31 12.4,50.31 12.15,50.06 12.15,49.84 v4(11.97,49.66)
WLAN_TX_Q_P: length 29.7
  TOP w0.058: U2901.27 12.27,51.22 12.27,50.67 12.33,50.61 12.42,50.61 12.48,50.55 12.48,50.44 12.42,50.38 12.33,50.38 12.27,50.32 12.27,50.14 v3(12.47,49.94)
  S3 w0.05: 32.71,40.44 32.71,40.43 32.71,40.43 32.71,39.43 v3(32.57,39.28)
  S3 w0.053: v4(12.45,49.66) 12.47,49.68 v3(12.47,49.94) ; 32.71,40.44 32.71,41.6 27.29,47.02 26.23,47.02 25.53,47.71 23.49,47.71 v4(23.31,47.53)
  S6 w0.053: v4(12.45,49.66) 12.27,49.84 12.27,50.01 12.45,50.19 14.05,50.19 16.2,48.04 22.32,48.04 22.66,47.7 23.14,47.7 v4(23.31,47.53)
WLAN_XO_CLK: length 93.1
  TOP w0.066: v3(13.55,47.85) 12.89,48.51 4.05,48.51 v3(3.99,48.57) ; C720.2 v3(28.21,12.5)
  S3 w0.064: v3(31.77,39.28) 31.77,39.49 31.66,39.6 31.66,39.79 31.76,39.89 31.76,41.59 27.88,45.47 26.13,45.47 25.68,45.92 22.84,45.92 22.43,46.33 21.51,46.33 v4(21.41,46.23) ; v3(13.55,47.85) 13.62,47.92 13.95,47.92 v4(13.99,47.96) ; v3(3.99,48.57) 3.99,15.8 7.49,12.29 12.53,12.29 13.52,11.3 27.01,11.3 v3(28.21,12.5)
  S6 w0.064: v4(13.99,47.96) 14.52,47.96 15.4,47.08 17.98,47.08 18.84,46.23 v4(21.41,46.23)
XO_THERM: length 8.9
  S3 w0.064: v3(32.65,9.1) 32.53,9.1 32.41,9.22 32.41,11.04 32.79,11.42 v3(33.52,11.42) 33.71,11.23 34.99,11.23 35.13,11.36 35.13,12.09 35.59,12.55 35.59,14.32 35.86,14.59 35.86,14.84 v3(35.86,14.85)
XOADC_GND: length 8.3
  TOP w0.1: Y701.2 32.64,10.16 v3(32.64,9.5)
  S3 w0.064: v3(32.64,9.5) 33.71,9.5 35.31,11.1 35.31,12.06 35.72,12.48 35.72,14.28 35.97,14.53 35.97,14.68 36.11,14.82 36.11,15.08 v3(36.13,15.08)
N20480751: length 3.3
  S3 w0.127: v3(43.81,16.01) 43.5,15.7 v3(40.67,15.7)
N20518421: length 3.2
  BOTTOM w0.066: U1102.5 17.09,32.08 17.32,32.31 C1106.1 18.98,32.32 R1102.2
N20519216: length 1.6
  BOTTOM w0.066: R1101.2 C1105.1 16.97,36.76 16.75,36.98 U1101.12

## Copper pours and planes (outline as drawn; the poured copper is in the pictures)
5V_BUCK_C on TOP (solid shape): 7.38,39.42 7.27,39.31 4.31,39.31 4.17,39.45 4.17,40.58 4.23,40.64 5.99,40.64 6.25,40.9 7.38,40.9
5V_BUCK_OUT on TOP (solid shape): 12.84,46.97 17.09,46.97 17.53,46.53 17.53,39.08 15.66,39.08 15.63,39.11 15.63,44.83 15.1,45.36 11.63,45.36 10.65,46.34 6.4,46.34 6.21,46.53 6.21,47.69 6.4,47.88 11.93,47.88
5V_BUCK_OUT on BOTTOM (solid shape): 7.84,49.05 7.84,47.3 7.69,47.15 5.3,47.15 5.19,47.26 5.19,49.03 5.33,49.17 7.72,49.17
5V_BUCK_OUT on S3 (solid shape): 7.72,48.37 7.72,46.94 7.6,46.82 6.32,46.82 6.24,46.9 6.24,48.43 6.29,48.48 7.61,48.48
5V_BUCK_OUT on S6 (solid shape): 7.65,49.13 7.65,47.53 7.62,47.5 6.41,47.5 6.29,47.62 6.29,49.14 6.34,49.19 7.59,49.19
5V_BUCK_SW on TOP (solid shape): 12.69,44.78 12.69,39.12 12.52,38.95 10.03,38.95 9.7,39.28 9.7,40.96 9.09,41.57 9.09,42.87 9.19,42.97 10.83,42.97 10.99,43.13 10.99,44.82 12.65,44.82
5V_BUCK_VIN on TOP (solid shape): 3.23,47.89 3.23,44.29 3.82,43.7 4.97,43.7 5.13,43.54 5.13,43.2 5.38,42.95 6.94,42.95 6.96,42.93 6.96,41.44 6.93,41.41 3.83,41.41 3.02,42.22 1.79,42.22 1.37,42.64 1.37,47.94 1.53,48.1 3.02,48.1
5V_BUCK_VIN on BOTTOM (solid shape): 3.23,50.71 3.23,48.77 3.13,48.67 1.46,48.67 1.39,48.74 1.39,50.66 1.51,50.78 3.16,50.78
5V_BUCK_VIN on S3 (solid shape): 2.83,48.85 2.83,47.31 2.75,47.23 1.51,47.23 1.39,47.35 1.39,48.83 1.61,49.05 2.63,49.05
5V_BUCK_VIN on S6 (solid shape): 2.79,51 2.79,48.13 2.62,47.96 1.48,47.96 1.39,48.05 1.39,51.02 1.51,51.14 2.65,51.14
5V_SYS on BOTTOM (solid shape): 12.38,13.57 12.38,10.5 12.25,10.37 10.54,10.37 10.33,10.58 10.33,13.56 10.5,13.73 12.22,13.73
5V_SYS on BOTTOM (solid shape): 11.46,52.2 11.46,49.84 11.77,49.53 13.09,49.53 14.14,48.48 14.14,45.38 14.46,45.05 14.46,44.16 14.65,43.98 14.65,42.71 13.01,42.71 12.81,42.91 12.81,46.66 12.25,47.22 9.4,47.22 9.11,47.51 9.11,52.28 9.3,52.47 11.19,52.47
5V_SYS on V4: 1.64,31.63 6.04,31.63 6.87,30.8 6.87,21.39 7.5,20.76 7.5,6.74 10.54,3.7 14,3.7 16.57,1.13 29.17,1.13 29.32,1.28 29.32,2.95 29.83,3.47 31.41,3.47 31.71,3.16 31.71,0.65 31.57,0.51 10.56,0.51 9.54,1.53 9.54,3.29 7.97,4.86 6.03,4.86 5.87,5.03 5.87,8.42 4.46,8.42 4.08,8.8 4.08,28.6 3.26,29.42 1.59,29.42 1.45,29.56 1.45,31.44
5V_SYS on S6: 6.48,46.95 7.55,46.95 7.67,46.83 7.67,44.3 7.28,43.91 6.08,43.91 4.85,42.68 4.85,34.39 6.16,33.08 6.16,30.51 5.22,29.57 0.99,29.57 0.89,29.67 0.89,43.13 1.88,44.12 3.1,44.12 3.38,44.4 3.38,44.4 4.17,45.19 5.97,45.19 6.29,45.51 6.29,46.76
5V_SYS on S6: 5.62,10.12 6,10.12 6.29,9.82 6.29,9.29 6.86,8.72 6.86,8.36 5.64,8.36 5.51,8.48 5.51,10.02
5V_SYS on G7: 10.83,50.14 9.61,50.14 9.4,49.93 9.4,48.91 7.83,47.35 7.19,47.35 6.9,47.06 6.9,46.09 7.04,45.96 8.95,45.96 11.03,48.04 11.03,49.94
5V_SYS on G7: 12.34,8.3 12.34,11.5 12.23,11.61 5.65,11.61 5.44,11.4 5.44,8.57 5.88,8.13 12.17,8.13
5V_USB_VBUS on BOTTOM (solid shape): 7.77,52.4 7.77,50.16 7.54,49.93 5.43,49.93 5.24,50.12 5.24,52.47 7.7,52.47
5V_USB_VBUS on S6 (solid shape): 16,43.92 16,42.82 15.98,42.8 15.04,42.8 14.96,42.88 14.96,43.94 15.09,44.07 15.85,44.07
5V_USB_VBUS on S3: 35.73,63.75 30.47,63.75 30.36,63.86 30.36,66.62 30.45,66.71 31.56,66.71 31.68,66.59 31.68,65.26 31.99,64.95 44.43,64.95 44.54,64.84 44.54,63.99 44.35,63.8 40.34,63.8 39.72,63.19 39.72,61.97 39.38,61.64 39.38,61.22 39.19,61.03 38.92,61.03 38.87,61.07 38.87,61.8 39.16,62.08 39.16,63.03 38.45,63.73 37.08,63.73 36.86,63.51 36.86,63.06 36.56,62.76 36.56,61.02 36.52,60.98 36.09,60.98 35.96,61.12 35.96,63.53
5V_USB_VBUS on V5: 15.57,42.85 13.56,42.85 11.3,45.11 5.56,45.11 5.46,45.21 5.46,46.52 5.55,46.61 11.66,46.61 14.07,44.2 15.7,44.2 15.7,42.98
5V_USB_VBUS on S6: 23.99,67.88 30.24,67.88 33.13,64.99 43.51,64.99 43.64,65.12 44.33,65.12 44.55,64.9 44.55,63.81 44.36,63.62 32.06,63.62 29.04,66.64 24.96,66.64 23.75,65.44 23.75,63.15 23.26,62.65 7.61,62.65 6.1,61.14 6.1,52.68 6.38,52.4 7.48,52.4 7.57,52.31 7.57,49.64 7.41,49.48 6.41,49.48 6.11,49.18 6.11,45.62 3.91,45.62 3.91,52.58 4.17,52.84 4.17,61.75 6.28,63.86 22.12,63.86 22.55,64.28 22.55,66.44
AVDD3P0V on TOP (solid shape): 30.4,56.9 32.33,56.9 32.51,56.72 32.51,56.39 32.41,56.29 29.84,56.29 29.24,56.9 28.17,56.9 27.94,56.67 27.3,56.67 27.28,56.69 27.28,57.81 27.33,57.86 29.44,57.86
DVDD1P0V on BOTTOM (solid shape): 39.38,52.48 39.38,51.59 38.73,51.59 38.54,51.4 37.01,51.4 36.97,51.44 36.97,52 37.12,52.15 37.5,52.15 37.59,52.24 37.59,52.65 37.65,52.71 39.15,52.71
DVDD1P0V on S6 (solid shape): 37.48,52.09 37.48,51.53 37.36,51.41 36.98,51.41 36.93,51.46 36.93,51.74 36.09,52.58 36.09,52.7 36.2,52.81 36.76,52.81
DVDD1P8V on BOTTOM (solid shape): 37.42,53.18 37.42,53 36.72,52.3 36.72,50.51 36.64,50.43 35.97,50.43 35.9,50.5 35.9,52.32 36.18,52.6 36.18,53.05 36.2,53.07 37.01,53.07 37.21,53.27 37.33,53.27
GND on TOP (solid shape): 8.71,41.79 7.41,41.79 7.41,44.3 8.71,44.3
GND on TOP (solid shape): 11.56,63.63 8.66,63.63 8.66,65.28 11.56,65.28
GND on TOP (solid shape): 41.54,30.14 41.64,30.14 41.64,29.14 41.65,29.1 41.67,29.06 41.73,29 41.77,28.97 41.82,28.97 42.86,28.97 42.9,28.94 42.9,28.89 42.86,28.83 42.85,28.76 42.86,28.68 42.9,28.62 42.91,28.57 42.86,28.54 42.08,28.54 42.07,28.54 41.71,28.54 41.43,28.82 41.43,30.1 41.45,30.14 41.5,30.14
GND on TOP (solid shape): 27.26,25.71 26.46,24.91 26.41,24.9 26.38,24.95 26.38,26.62 26.56,26.62 26.61,26.64 26.63,26.7 26.63,26.92 26.67,26.96 26.7,26.96 26.71,26.94 26.71,26.7 26.73,26.66 26.76,26.65 27.07,26.65 27.1,26.66 27.12,26.7 27.12,27 27.1,27.04 27.07,27.05 26.76,27.05 26.74,27.05 26.7,27.05 26.68,27.09 26.68,28.19 27.26,28.19
GND on TOP (solid shape): 23.98,33.31 23.99,33.26 23.95,33.23 23.88,33.23 23.55,33.55 23.52,33.57 23.48,33.58 22.74,33.58 22.7,33.57 22.67,33.55 21.93,32.82 21.88,32.81 21.85,32.85 21.85,32.91 22.19,33.26 22.23,33.31 22.24,33.37 22.24,33.59 22.26,33.63 22.31,33.63 22.38,33.61 22.45,33.6 22.64,33.66 22.76,33.82 23.47,33.82
GND on TOP (solid shape): 37.26,38.72 37.3,38.69 37.3,38.64 37.26,38.58 37.25,38.51 37.29,38.38 37.4,38.3 37.42,38.3 37.42,38.26 37.35,38.26 37.3,38.25 37.26,38.22 36.91,37.87 36.59,37.87 36.54,37.86 36.5,37.83 36.18,37.51 35.74,37.51 35.66,37.5 35.66,37.56 35.97,37.56 36.02,37.57 36.06,37.6 36.46,38.01 36.8,38.01 36.85,38.02 36.89,38.04 36.99,38.14 37.01,38.18 37.02,38.23 37.02,38.57 37.18,38.72
GND on TOP (solid shape): outline of 83 points within 21.13,37.32 31.1,41.91
GND on TOP (solid shape): 34.14,63.72 34.19,63.69 34.17,63.63 34,63.45 33.94,63.21 33.95,63.15 33.95,63.09 33.95,63.05 33.91,63.03 33.68,63.03 33.6,63.03 33.53,63.03 33.08,62.85 32.9,62.41 32.9,61.31 33.53,60.68 34.15,61.31 34.15,61.7 34.51,61.95 34.65,62.36 34.63,62.51 34.58,62.66 34.58,62.7 34.61,62.73 34.76,62.81 34.87,62.93 34.92,62.95 34.96,62.91 34.96,62.06 35,61.97 35.09,61.93 36.27,61.93 36.31,61.89 36.28,61.83 34.84,61.83 34.75,61.8 34.71,61.71 34.71,60.76 34.75,60.67 34.84,60.63 35.36,60.63 35.4,60.6 35.39,60.55 35.03,60.19 32.53,60.19 32.47,60.18 32.42,60.14 32.21,59.93 31.87,59.93 31.85,59.96 31.85,60.05 31.84,60.09 31.82,60.13 31.81,60.15 31.82,60.17 31.84,60.21 31.85,60.25 31.85,60.65 31.84,60.69 31.82,60.73 31.81,60.75 31.82,60.77 31.84,60.81 31.85,60.85 31.85,60.96 31.86,60.98 32.12,60.98 32.18,60.99 32.23,61.02 32.45,61.24 32.48,61.29 32.49,61.35 32.49,62.88 33.34,63.72
GND on TOP (solid shape): outline of 112 points within 33.4,54.54 37.36,58.08
GND on TOP (solid shape): outline of 125 points within 3.13,43.14 6.93,48.24
GND on TOP (solid shape): outline of 210 points within 44.77,27.9 45.86,30.52
GND on TOP (solid shape): outline of 153 points within 30.02,56.9 36.63,59.95
GND on TOP (solid shape): outline of 297 points within 42.27,34.42 46.51,36.44
GND on TOP (solid shape): outline of 247 points within 21.62,36.48 24.08,40.26
GND on S3 (solid shape): 40.28,41.35 40.32,41.37 40.36,41.34 40.38,41.28 40.42,41.23 40.42,41.11 40.46,40.98 40.57,40.89 40.61,40.86 40.59,40.81 40.44,40.66 40.44,40.35 40.58,40.21 40.97,40.21 41.07,40.1 41.07,39.76 40.91,39.59 40.33,39.59 40.3,39.57 40.25,39.55 40.22,39.6 40.22,40.54 40.21,40.58 40.18,40.61 40.03,40.77 40.02,40.82 40.06,40.85 40.1,40.85 40.23,40.99 40.23,41.31
GND on S3 (solid shape): outline of 181 points within 39.97,36.97 43.87,39.14
GND on S3 (solid shape): outline of 100 points within 36.64,37.66 40,39.92
GND on S3 (solid shape): outline of 223 points within 35.61,43.48 37.99,51.87
GND on S3 (solid shape): outline of 337 points within 38.84,35.7 43.88,37.6
GND on S3 (solid shape): outline of 379 points within 42.7,33.52 46.78,41.55
GND on S3 (solid shape): outline of 645 points within 13,38.49 21.21,52.46
GND on S3 (solid shape): outline of 18483 points within 0.51,0.51 52.83,68.07
GND on BOTTOM, V4, V5, G7: 1,3.05 0.65,3.19 0.51,3.54 0.51,67.58 0.65,67.93 1,68.07 52.34,68.07 52.69,67.93 52.83,67.58 52.83,4.27 51.61,3.05 40.18,3.05 37.64,0.51 5.29,0.51 2.75,3.05
GND on G2: 1,3.05 0.65,3.19 0.51,3.54 0.51,67.58 0.65,67.93 1,68.07 52.34,68.07 52.69,67.93 52.83,67.58 52.83,4.27 51.61,3.05 40.18,3.05 37.64,0.51 5.29,0.51 2.75,3.05 ; 2 cut-outs
VBAT on BOTTOM (solid shape): 8.28,13.28 8.61,12.95 8.61,11.15 6.93,11.15 6.93,14.09 7.17,14.33 8.28,14.33
VBAT on BOTTOM (solid shape): 8.56,40.61 8.56,39.55 8.43,39.42 6.73,39.42 6.56,39.59 6.56,40.6 6.8,40.84 8.33,40.84
VBAT on S6 (solid shape): 8.27,40.67 8.27,39.68 8.18,39.59 6.34,39.59 6.18,39.75 6.18,40.68 6.34,40.84 8.1,40.84
VBAT on S6 (solid shape): 15.79,7.24 15.79,6.64 15.63,6.48 14.32,6.48 13.67,7.14 13.67,7.49 13.92,7.75 15.28,7.75
VBAT on TOP: 45.56,16.16 46.59,16.16 46.59,15.16 46.49,15.06 44.93,15.06 44.93,15.06 41.91,15.06 41.61,14.76 41.45,14.76 41.15,15.06 41.15,15.29 41.55,15.7 44.55,15.7 44.86,16 45.4,16
VBAT on S3: 45.59,15.79 45.59,14.78 47.07,14.78 47.07,15.79
VBAT on V5: 5.33,40.72 5.33,33.3 8.92,29.72 8.92,19.18 6.6,16.87 6.6,15.88 5.95,15.23 5.95,9.3 6.6,8.65 6.6,7.57 10.72,3.45 22.07,3.45 24.94,6.32 48.18,6.32 49.28,7.42 49.28,15.43 48.54,16.17 45.95,16.17 45.62,15.84 45.62,14.97 47.17,13.42 47.17,11.1 45.01,8.94 23.06,8.94 20.5,6.38 17.78,6.38 16.61,7.54 14.02,7.54 12.17,9.4 12.17,31.39 8.6,34.96 8.6,40.69 8.27,41.02 5.64,41.02
VBAT on G7: 15.88,15.16 16.51,14.53 16.51,7.05 16.35,6.89 13.08,6.89 12.68,7.29 12.68,11.53 12.42,11.79 7.59,11.79 7.04,12.34 7.04,14.99 7.21,15.16
(no net) on TOP, S6: 1,3.05 0.65,3.19 0.51,3.54 0.51,67.58 0.65,67.93 1,68.07 52.34,68.07 52.69,67.93 52.83,67.58 52.83,4.27 51.61,3.05 40.18,3.05 37.64,0.51 5.29,0.51 2.75,3.05
(no net) on G2: 1,3.04 0.65,3.19 0.51,3.54 0.51,67.58 0.65,67.93 1,68.08 52.34,68.08 52.69,67.93 52.84,67.58 52.84,4.27 51.61,3.04 40.18,3.04 37.64,0.51 5.29,0.51 2.75,3.04
(no net) on S3: 1,3.05 0.65,3.19 0.51,3.54 0.51,67.58 0.65,67.93 1,68.07 52.34,68.07 52.69,67.93 52.83,67.58 52.83,4.27 51.61,3.05 40.18,3.05 37.64,0.51 5.29,0.51 2.75,3.05 ; 1 cut-out
(no net) on S3, S6: 1,68.58 0.29,68.29 0,67.58 0,3.54 0.29,2.83 1,2.54 2.54,2.54 5.08,0 37.85,0 40.39,2.54 51.82,2.54 53.34,4.06 53.34,67.58 53.05,68.29 52.34,68.58
DC_IN on BOTTOM (solid shape): 5.11,46.53 5.11,44.27 5.04,44.2 1.55,44.2 1.38,44.37 1.38,46.53 1.47,46.62 5.02,46.62
DC_IN on BOTTOM (solid shape): 7.63,57.26 7.63,56.02 7.8,55.85 9.88,55.85 9.88,54.15 9.76,54.03 5.3,54.03 5.14,54.19 5.14,57.23 5.36,57.45 7.44,57.45
DC_IN on S6 (solid shape): 3.47,46.03 3.47,45.12 3.28,44.93 1.68,44.93 1.44,45.17 1.44,46.13 1.55,46.24 3.26,46.24
DC_IN on S6 (solid shape): 7.66,55.66 7.66,54.25 7.53,54.12 6.42,54.12 6.3,54.24 6.3,55.61 6.52,55.83 7.49,55.83
DC_IN on S3: 7.5,55.82 6.31,55.82 6.19,55.7 6.19,54.16 6.26,54.09 7.49,54.09 7.56,54.16 7.56,55.76
DC_IN on V5: 1.7,21.32 3.6,21.32 4.07,21.79 4.07,48.54 6.34,50.81 6.34,53.44 6.71,53.81 7.96,53.81 8.04,53.89 8.04,55.45 7.55,55.93 5.23,55.93 4.32,55.02 4.32,54.27 2.64,52.59 1.75,52.59 1.14,51.98 1.14,21.88
LDO1_LX on BOTTOM (solid shape): 12.42,46.28 12.42,42.8 12.29,42.67 11,42.67 10.9,42.77 10.9,46.3 11.05,46.46 12.24,46.46
LDO2_LX on BOTTOM (solid shape): 11.23,38.33 11.23,34.75 9.98,34.75 9.91,34.82 9.91,38.61 9.98,38.68 10.88,38.68
PWR_3P3V on BOTTOM (solid shape): 12.42,8.88 12.42,4.87 12.26,4.71 10.64,4.71 10.44,4.91 10.44,8.93 12.37,8.93
PWR_3P3V on BOTTOM (solid shape): 9.89,61.23 9.89,58 7.77,58 7.62,58.15 7.62,61.22 7.76,61.36 9.76,61.36
PWR_3P3V on BOTTOM (solid shape): 9.2,38.79 9.2,35.88 9.39,35.69 9.39,34.74 9.29,34.64 8.23,34.64 7.82,34.23 7.82,33.11 8.57,32.36 8.57,31.37 8.82,31.12 13.85,31.12 14.4,31.67 15.4,31.67 15.79,32.06 16.43,32.06 16.54,31.95 16.54,29.56 16.41,29.43 12.53,29.43 11.94,30.02 8.66,30.02 8.03,30.65 7.95,30.65 7.39,30.65 6.69,31.35 4.52,31.35 3.76,32.11 2.16,32.11 1.57,32.7 1.57,33.82 1.98,34.23 5.57,34.23 6.98,35.64 6.98,36.35 7.11,36.48 7.65,36.48 7.82,36.65 7.82,37.68 7.56,37.94 6.64,37.94 6.49,38.09 6.49,38.6 6.55,38.66 7.81,38.66 7.92,38.77 7.92,39.14 8.85,39.14
PWR_3P3V on S3 (solid shape): 27.46,65.93 27.46,65.27 27.35,65.16 26.57,65.16 26.2,65.52 26.2,65.86 26.33,65.99 27.4,65.99
PWR_3P3V on S6 (solid shape): 12.43,4.83 12.43,4.1 12.22,3.89 10.85,3.89 10.46,4.28 10.46,5 10.54,5.08 12.18,5.08
PWR_3P3V on S6 (solid shape): 10.02,61.66 10.02,60.72 9.85,60.55 8.82,60.55 8.63,60.74 8.63,61.65 8.84,61.86 9.81,61.86
PWR_3P3V on S6 (solid shape): 28.27,65.95 28.27,65.09 28.2,65.01 25.35,65.01 25.28,65.08 25.28,65.91 25.4,66.03 28.19,66.03
PWR_3P3V on G7 (solid shape): 26.26,65.9 26.26,65.12 26.15,65.01 25.35,65.01 25.28,65.08 25.28,65.91 25.4,66.03 26.13,66.03
PWR_3P3V on V4: 7.11,21.74 7.11,25.04 7.58,25.51 7.58,31.4 7.18,31.8 1.82,31.8 1.38,32.24 1.38,39.03 1.56,39.21 7.57,39.21 7.79,38.99 7.79,36.27 10.04,34.02 10.04,30.47 10.26,30.25 12.96,30.25 13.58,29.63 13.58,14.42 15.75,12.25 15.75,5.08 14.44,3.77 10.56,3.77 7.79,6.54 7.79,21.06
